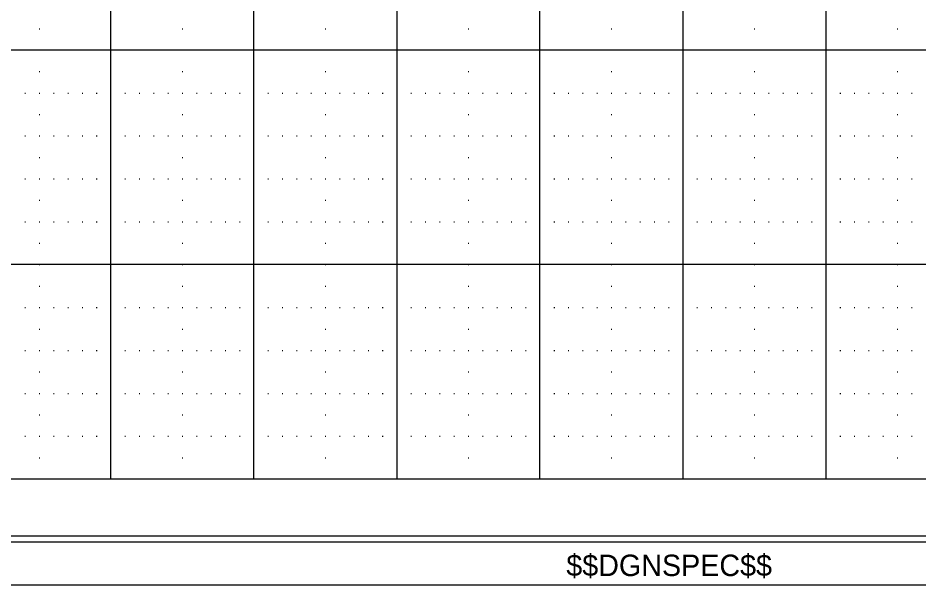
# Model space of a CAD drawing. Extents: x -1.3 to 32, y -0.2 to 20.7.
# Drawn here: x 23.679 to 27.879, y -0.229 to 2.414 of the extents above; entities that cross this region are included whole.
import ezdxf

# ---------------------------------------------------------------- set-up
doc = ezdxf.new("R2010")
doc.units = 0
for name, color, linetype in [('Level 1', 7, 'Continuous'), ('Level 37', 7, 'Continuous'), ('Level 4', 7, 'Continuous'), ('Level 48', 7, 'Continuous'), ('Level 5', 7, 'Continuous'), ('Level 62', 7, 'Continuous'), ('Level 63', 7, 'Continuous')]:
    doc.layers.add(name, color=color, linetype=linetype)

msp = doc.modelspace()

# ---------------------------------------------------------------- linework, layer by layer
at = {"layer": 'Level 1'}
msp.add_line((31.588, -0.03), (-0.03, -0.03), dxfattribs=at)
at = {"layer": 'Level 37'}
msp.add_line((31.1123, 0.264), (0.7787, 0.2635), dxfattribs=at)
at = {"layer": 'Level 4'}
for p, q in [((24.1123, 0.264), (24.1123, 10.264)), ((24.779, 0.264), (24.779, 10.264)), ((25.4457, 0.264), (25.4457, 10.264)), ((26.1123, 0.264), (26.1123, 10.264)), ((26.779, 0.264), (26.779, 10.264)), ((27.4457, 0.264), (27.4457, 10.264)), ((31.588, 2.264), (-0.03, 2.264)), ((31.588, 1.264), (-0.03, 1.264)), ((31.588, 0.264), (0.4456, 0.264))]:
    msp.add_line(p, q, dxfattribs=at)
at = {"layer": 'Level 5'}
for p, q in [((23.7773, 2.364), (23.7807, 2.364)), ((24.444, 2.364), (24.4473, 2.364)), ((25.1107, 2.364), (25.114, 2.364)), ((25.7773, 2.364), (25.7807, 2.364)), ((26.444, 2.364), (26.4473, 2.364)), ((27.1107, 2.364), (27.114, 2.364)), ((27.7773, 2.364), (27.7807, 2.364)), ((23.7773, 2.164), (23.7807, 2.164)), ((24.444, 2.164), (24.4473, 2.164)), ((25.1107, 2.164), (25.114, 2.164)), ((25.7773, 2.164), (25.7807, 2.164)), ((26.444, 2.164), (26.4473, 2.164)), ((27.1107, 2.164), (27.114, 2.164)), ((27.7773, 2.164), (27.7807, 2.164)), ((23.7107, 2.064), (23.714, 2.064)), ((23.7773, 2.064), (23.7807, 2.064)), ((23.844, 2.064), (23.8473, 2.064)), ((23.9107, 2.064), (23.914, 2.064)), ((23.9773, 2.064), (23.9807, 2.064)), ((24.044, 2.064), (24.0473, 2.064)), ((24.1773, 2.064), (24.1807, 2.064)), ((24.244, 2.064), (24.2473, 2.064)), ((24.3107, 2.064), (24.314, 2.064)), ((24.3773, 2.064), (24.3807, 2.064)), ((24.444, 2.064), (24.4473, 2.064)), ((24.5107, 2.064), (24.514, 2.064)), ((24.5773, 2.064), (24.5807, 2.064)), ((24.644, 2.064), (24.6473, 2.064)), ((24.7107, 2.064), (24.714, 2.064)), ((24.844, 2.064), (24.8473, 2.064)), ((24.9107, 2.064), (24.914, 2.064)), ((24.9773, 2.064), (24.9807, 2.064)), ((25.044, 2.064), (25.0473, 2.064)), ((25.1107, 2.064), (25.114, 2.064)), ((25.1773, 2.064), (25.1807, 2.064)), ((25.244, 2.064), (25.2473, 2.064)), ((25.3107, 2.064), (25.314, 2.064)), ((25.3773, 2.064), (25.3807, 2.064)), ((25.5107, 2.064), (25.514, 2.064)), ((25.5773, 2.064), (25.5807, 2.064)), ((25.644, 2.064), (25.6473, 2.064)), ((25.7107, 2.064), (25.714, 2.064)), ((25.7773, 2.064), (25.7807, 2.064)), ((25.844, 2.064), (25.8473, 2.064)), ((25.9107, 2.064), (25.914, 2.064)), ((25.9773, 2.064), (25.9807, 2.064)), ((26.044, 2.064), (26.0473, 2.064)), ((26.1773, 2.064), (26.1807, 2.064)), ((26.244, 2.064), (26.2473, 2.064)), ((26.3107, 2.064), (26.314, 2.064)), ((26.3773, 2.064), (26.3807, 2.064)), ((26.444, 2.064), (26.4473, 2.064)), ((26.5107, 2.064), (26.514, 2.064)), ((26.5773, 2.064), (26.5807, 2.064)), ((26.644, 2.064), (26.6473, 2.064)), ((26.7107, 2.064), (26.714, 2.064)), ((26.844, 2.064), (26.8473, 2.064)), ((26.9107, 2.064), (26.914, 2.064)), ((26.9773, 2.064), (26.9807, 2.064)), ((27.044, 2.064), (27.0473, 2.064)), ((27.1107, 2.064), (27.114, 2.064)), ((27.1773, 2.064), (27.1807, 2.064)), ((27.244, 2.064), (27.2473, 2.064)), ((27.3107, 2.064), (27.314, 2.064)), ((27.3773, 2.064), (27.3807, 2.064)), ((27.5107, 2.064), (27.514, 2.064)), ((27.5773, 2.064), (27.5807, 2.064)), ((27.644, 2.064), (27.6473, 2.064)), ((27.7107, 2.064), (27.714, 2.064)), ((27.7773, 2.064), (27.7807, 2.064)), ((27.844, 2.064), (27.8473, 2.064)), ((23.7773, 1.964), (23.7807, 1.964)), ((24.444, 1.964), (24.4473, 1.964)), ((25.1107, 1.964), (25.114, 1.964)), ((25.7773, 1.964), (25.7807, 1.964)), ((26.444, 1.964), (26.4473, 1.964)), ((27.1107, 1.964), (27.114, 1.964)), ((27.7773, 1.964), (27.7807, 1.964)), ((23.7107, 1.864), (23.714, 1.864)), ((23.7773, 1.864), (23.7807, 1.864)), ((23.844, 1.864), (23.8473, 1.864)), ((23.9107, 1.864), (23.914, 1.864)), ((23.9773, 1.864), (23.9807, 1.864)), ((24.044, 1.864), (24.0473, 1.864)), ((24.1773, 1.864), (24.1807, 1.864)), ((24.244, 1.864), (24.2473, 1.864)), ((24.3107, 1.864), (24.314, 1.864)), ((24.3773, 1.864), (24.3807, 1.864)), ((24.444, 1.864), (24.4473, 1.864)), ((24.5107, 1.864), (24.514, 1.864)), ((24.5773, 1.864), (24.5807, 1.864)), ((24.644, 1.864), (24.6473, 1.864)), ((24.7107, 1.864), (24.714, 1.864)), ((24.844, 1.864), (24.8473, 1.864)), ((24.9107, 1.864), (24.914, 1.864)), ((24.9773, 1.864), (24.9807, 1.864)), ((25.044, 1.864), (25.0473, 1.864)), ((25.1107, 1.864), (25.114, 1.864)), ((25.1773, 1.864), (25.1807, 1.864)), ((25.244, 1.864), (25.2473, 1.864)), ((25.3107, 1.864), (25.314, 1.864)), ((25.3773, 1.864), (25.3807, 1.864)), ((25.5107, 1.864), (25.514, 1.864)), ((25.5773, 1.864), (25.5807, 1.864)), ((25.644, 1.864), (25.6473, 1.864)), ((25.7107, 1.864), (25.714, 1.864)), ((25.7773, 1.864), (25.7807, 1.864)), ((25.844, 1.864), (25.8473, 1.864)), ((25.9107, 1.864), (25.914, 1.864)), ((25.9773, 1.864), (25.9807, 1.864)), ((26.044, 1.864), (26.0473, 1.864)), ((26.1773, 1.864), (26.1807, 1.864)), ((26.244, 1.864), (26.2473, 1.864)), ((26.3107, 1.864), (26.314, 1.864)), ((26.3773, 1.864), (26.3807, 1.864)), ((26.444, 1.864), (26.4473, 1.864)), ((26.5107, 1.864), (26.514, 1.864)), ((26.5773, 1.864), (26.5807, 1.864)), ((26.644, 1.864), (26.6473, 1.864)), ((26.7107, 1.864), (26.714, 1.864)), ((26.844, 1.864), (26.8473, 1.864)), ((26.9107, 1.864), (26.914, 1.864)), ((26.9773, 1.864), (26.9807, 1.864)), ((27.044, 1.864), (27.0473, 1.864)), ((27.1107, 1.864), (27.114, 1.864)), ((27.1773, 1.864), (27.1807, 1.864)), ((27.244, 1.864), (27.2473, 1.864)), ((27.3107, 1.864), (27.314, 1.864)), ((27.3773, 1.864), (27.3807, 1.864)), ((27.5107, 1.864), (27.514, 1.864)), ((27.5773, 1.864), (27.5807, 1.864)), ((27.644, 1.864), (27.6473, 1.864)), ((27.7107, 1.864), (27.714, 1.864)), ((27.7773, 1.864), (27.7807, 1.864)), ((27.844, 1.864), (27.8473, 1.864)), ((23.7773, 1.764), (23.7807, 1.764)), ((24.444, 1.764), (24.4473, 1.764)), ((25.1107, 1.764), (25.114, 1.764)), ((25.7773, 1.764), (25.7807, 1.764)), ((26.444, 1.764), (26.4473, 1.764)), ((27.1107, 1.764), (27.114, 1.764)), ((27.7773, 1.764), (27.7807, 1.764)), ((23.7107, 1.664), (23.714, 1.664)), ((23.7773, 1.664), (23.7807, 1.664)), ((23.844, 1.664), (23.8473, 1.664)), ((23.9107, 1.664), (23.914, 1.664)), ((23.9773, 1.664), (23.9807, 1.664)), ((24.044, 1.664), (24.0473, 1.664)), ((24.1773, 1.664), (24.1807, 1.664)), ((24.244, 1.664), (24.2473, 1.664)), ((24.3107, 1.664), (24.314, 1.664)), ((24.3773, 1.664), (24.3807, 1.664)), ((24.444, 1.664), (24.4473, 1.664)), ((24.5107, 1.664), (24.514, 1.664)), ((24.5773, 1.664), (24.5807, 1.664)), ((24.644, 1.664), (24.6473, 1.664)), ((24.7107, 1.664), (24.714, 1.664)), ((24.844, 1.664), (24.8473, 1.664)), ((24.9107, 1.664), (24.914, 1.664)), ((24.9773, 1.664), (24.9807, 1.664)), ((25.044, 1.664), (25.0473, 1.664)), ((25.1107, 1.664), (25.114, 1.664)), ((25.1773, 1.664), (25.1807, 1.664)), ((25.244, 1.664), (25.2473, 1.664)), ((25.3107, 1.664), (25.314, 1.664)), ((25.3773, 1.664), (25.3807, 1.664)), ((25.5107, 1.664), (25.514, 1.664)), ((25.5773, 1.664), (25.5807, 1.664)), ((25.644, 1.664), (25.6473, 1.664)), ((25.7107, 1.664), (25.714, 1.664)), ((25.7773, 1.664), (25.7807, 1.664)), ((25.844, 1.664), (25.8473, 1.664)), ((25.9107, 1.664), (25.914, 1.664)), ((25.9773, 1.664), (25.9807, 1.664)), ((26.044, 1.664), (26.0473, 1.664)), ((26.1773, 1.664), (26.1807, 1.664)), ((26.244, 1.664), (26.2473, 1.664)), ((26.3107, 1.664), (26.314, 1.664)), ((26.3773, 1.664), (26.3807, 1.664)), ((26.444, 1.664), (26.4473, 1.664)), ((26.5107, 1.664), (26.514, 1.664)), ((26.5773, 1.664), (26.5807, 1.664)), ((26.644, 1.664), (26.6473, 1.664)), ((26.7107, 1.664), (26.714, 1.664)), ((26.844, 1.664), (26.8473, 1.664)), ((26.9107, 1.664), (26.914, 1.664)), ((26.9773, 1.664), (26.9807, 1.664)), ((27.044, 1.664), (27.0473, 1.664)), ((27.1107, 1.664), (27.114, 1.664)), ((27.1773, 1.664), (27.1807, 1.664)), ((27.244, 1.664), (27.2473, 1.664)), ((27.3107, 1.664), (27.314, 1.664)), ((27.3773, 1.664), (27.3807, 1.664)), ((27.5107, 1.664), (27.514, 1.664)), ((27.5773, 1.664), (27.5807, 1.664)), ((27.644, 1.664), (27.6473, 1.664)), ((27.7107, 1.664), (27.714, 1.664)), ((27.7773, 1.664), (27.7807, 1.664)), ((27.844, 1.664), (27.8473, 1.664)), ((23.7773, 1.564), (23.7807, 1.564)), ((24.444, 1.564), (24.4473, 1.564)), ((25.1107, 1.564), (25.114, 1.564)), ((25.7773, 1.564), (25.7807, 1.564)), ((26.444, 1.564), (26.4473, 1.564)), ((27.1107, 1.564), (27.114, 1.564)), ((27.7773, 1.564), (27.7807, 1.564)), ((23.7107, 1.464), (23.714, 1.464)), ((23.7773, 1.464), (23.7807, 1.464)), ((23.844, 1.464), (23.8473, 1.464)), ((23.9107, 1.464), (23.914, 1.464)), ((23.9773, 1.464), (23.9807, 1.464)), ((24.044, 1.464), (24.0473, 1.464)), ((24.1773, 1.464), (24.1807, 1.464)), ((24.244, 1.464), (24.2473, 1.464)), ((24.3107, 1.464), (24.314, 1.464)), ((24.3773, 1.464), (24.3807, 1.464)), ((24.444, 1.464), (24.4473, 1.464)), ((24.5107, 1.464), (24.514, 1.464)), ((24.5773, 1.464), (24.5807, 1.464)), ((24.644, 1.464), (24.6473, 1.464)), ((24.7107, 1.464), (24.714, 1.464)), ((24.844, 1.464), (24.8473, 1.464)), ((24.9107, 1.464), (24.914, 1.464)), ((24.9773, 1.464), (24.9807, 1.464)), ((25.044, 1.464), (25.0473, 1.464)), ((25.1107, 1.464), (25.114, 1.464)), ((25.1773, 1.464), (25.1807, 1.464)), ((25.244, 1.464), (25.2473, 1.464)), ((25.3107, 1.464), (25.314, 1.464)), ((25.3773, 1.464), (25.3807, 1.464)), ((25.5107, 1.464), (25.514, 1.464)), ((25.5773, 1.464), (25.5807, 1.464)), ((25.644, 1.464), (25.6473, 1.464)), ((25.7107, 1.464), (25.714, 1.464)), ((25.7773, 1.464), (25.7807, 1.464)), ((25.844, 1.464), (25.8473, 1.464)), ((25.9107, 1.464), (25.914, 1.464)), ((25.9773, 1.464), (25.9807, 1.464)), ((26.044, 1.464), (26.0473, 1.464)), ((26.1773, 1.464), (26.1807, 1.464)), ((26.244, 1.464), (26.2473, 1.464)), ((26.3107, 1.464), (26.314, 1.464)), ((26.3773, 1.464), (26.3807, 1.464)), ((26.444, 1.464), (26.4473, 1.464)), ((26.5107, 1.464), (26.514, 1.464)), ((26.5773, 1.464), (26.5807, 1.464)), ((26.644, 1.464), (26.6473, 1.464)), ((26.7107, 1.464), (26.714, 1.464)), ((26.844, 1.464), (26.8473, 1.464)), ((26.9107, 1.464), (26.914, 1.464)), ((26.9773, 1.464), (26.9807, 1.464)), ((27.044, 1.464), (27.0473, 1.464)), ((27.1107, 1.464), (27.114, 1.464)), ((27.1773, 1.464), (27.1807, 1.464)), ((27.244, 1.464), (27.2473, 1.464)), ((27.3107, 1.464), (27.314, 1.464)), ((27.3773, 1.464), (27.3807, 1.464)), ((27.5107, 1.464), (27.514, 1.464)), ((27.5773, 1.464), (27.5807, 1.464)), ((27.644, 1.464), (27.6473, 1.464)), ((27.7107, 1.464), (27.714, 1.464)), ((27.7773, 1.464), (27.7807, 1.464)), ((27.844, 1.464), (27.8473, 1.464)), ((23.7773, 1.364), (23.7807, 1.364)), ((24.444, 1.364), (24.4473, 1.364)), ((25.1107, 1.364), (25.114, 1.364)), ((25.7773, 1.364), (25.7807, 1.364)), ((26.444, 1.364), (26.4473, 1.364)), ((27.1107, 1.364), (27.114, 1.364)), ((27.7773, 1.364), (27.7807, 1.364)), ((23.7773, 1.264), (23.7807, 1.264)), ((24.444, 1.264), (24.4473, 1.264)), ((25.1107, 1.264), (25.114, 1.264)), ((25.7773, 1.264), (25.7807, 1.264)), ((26.444, 1.264), (26.4473, 1.264)), ((27.1107, 1.264), (27.114, 1.264)), ((27.7773, 1.264), (27.7807, 1.264)), ((23.7773, 1.164), (23.7807, 1.164)), ((24.444, 1.164), (24.4473, 1.164)), ((25.1107, 1.164), (25.114, 1.164)), ((25.7773, 1.164), (25.7807, 1.164)), ((26.444, 1.164), (26.4473, 1.164)), ((27.1107, 1.164), (27.114, 1.164)), ((27.7773, 1.164), (27.7807, 1.164)), ((23.7107, 1.064), (23.714, 1.064)), ((23.7773, 1.064), (23.7807, 1.064)), ((23.844, 1.064), (23.8473, 1.064)), ((23.9107, 1.064), (23.914, 1.064)), ((23.9773, 1.064), (23.9807, 1.064)), ((24.044, 1.064), (24.0473, 1.064)), ((24.1773, 1.064), (24.1807, 1.064)), ((24.244, 1.064), (24.2473, 1.064)), ((24.3107, 1.064), (24.314, 1.064)), ((24.3773, 1.064), (24.3807, 1.064)), ((24.444, 1.064), (24.4473, 1.064)), ((24.5107, 1.064), (24.514, 1.064)), ((24.5773, 1.064), (24.5807, 1.064)), ((24.644, 1.064), (24.6473, 1.064)), ((24.7107, 1.064), (24.714, 1.064)), ((24.844, 1.064), (24.8473, 1.064)), ((24.9107, 1.064), (24.914, 1.064)), ((24.9773, 1.064), (24.9807, 1.064)), ((25.044, 1.064), (25.0473, 1.064)), ((25.1107, 1.064), (25.114, 1.064)), ((25.1773, 1.064), (25.1807, 1.064)), ((25.244, 1.064), (25.2473, 1.064)), ((25.3107, 1.064), (25.314, 1.064)), ((25.3773, 1.064), (25.3807, 1.064)), ((25.5107, 1.064), (25.514, 1.064)), ((25.5773, 1.064), (25.5807, 1.064)), ((25.644, 1.064), (25.6473, 1.064)), ((25.7107, 1.064), (25.714, 1.064)), ((25.7773, 1.064), (25.7807, 1.064)), ((25.844, 1.064), (25.8473, 1.064)), ((25.9107, 1.064), (25.914, 1.064)), ((25.9773, 1.064), (25.9807, 1.064)), ((26.044, 1.064), (26.0473, 1.064)), ((26.1773, 1.064), (26.1807, 1.064)), ((26.244, 1.064), (26.2473, 1.064)), ((26.3107, 1.064), (26.314, 1.064)), ((26.3773, 1.064), (26.3807, 1.064)), ((26.444, 1.064), (26.4473, 1.064)), ((26.5107, 1.064), (26.514, 1.064)), ((26.5773, 1.064), (26.5807, 1.064)), ((26.644, 1.064), (26.6473, 1.064)), ((26.7107, 1.064), (26.714, 1.064)), ((26.844, 1.064), (26.8473, 1.064)), ((26.9107, 1.064), (26.914, 1.064)), ((26.9773, 1.064), (26.9807, 1.064)), ((27.044, 1.064), (27.0473, 1.064)), ((27.1107, 1.064), (27.114, 1.064)), ((27.1773, 1.064), (27.1807, 1.064)), ((27.244, 1.064), (27.2473, 1.064)), ((27.3107, 1.064), (27.314, 1.064)), ((27.3773, 1.064), (27.3807, 1.064)), ((27.5107, 1.064), (27.514, 1.064)), ((27.5773, 1.064), (27.5807, 1.064)), ((27.644, 1.064), (27.6473, 1.064)), ((27.7107, 1.064), (27.714, 1.064)), ((27.7773, 1.064), (27.7807, 1.064)), ((27.844, 1.064), (27.8473, 1.064)), ((23.7773, 0.964), (23.7807, 0.964)), ((24.444, 0.964), (24.4473, 0.964)), ((25.1107, 0.964), (25.114, 0.964)), ((25.7773, 0.964), (25.7807, 0.964)), ((26.444, 0.964), (26.4473, 0.964)), ((27.1107, 0.964), (27.114, 0.964)), ((27.7773, 0.964), (27.7807, 0.964)), ((23.7107, 0.864), (23.714, 0.864)), ((23.7773, 0.864), (23.7807, 0.864)), ((23.844, 0.864), (23.8473, 0.864)), ((23.9107, 0.864), (23.914, 0.864)), ((23.9773, 0.864), (23.9807, 0.864)), ((24.044, 0.864), (24.0473, 0.864)), ((24.1773, 0.864), (24.1807, 0.864)), ((24.244, 0.864), (24.2473, 0.864)), ((24.3107, 0.864), (24.314, 0.864)), ((24.3773, 0.864), (24.3807, 0.864)), ((24.444, 0.864), (24.4473, 0.864)), ((24.5107, 0.864), (24.514, 0.864)), ((24.5773, 0.864), (24.5807, 0.864)), ((24.644, 0.864), (24.6473, 0.864)), ((24.7107, 0.864), (24.714, 0.864)), ((24.844, 0.864), (24.8473, 0.864)), ((24.9107, 0.864), (24.914, 0.864)), ((24.9773, 0.864), (24.9807, 0.864)), ((25.044, 0.864), (25.0473, 0.864)), ((25.1107, 0.864), (25.114, 0.864)), ((25.1773, 0.864), (25.1807, 0.864)), ((25.244, 0.864), (25.2473, 0.864)), ((25.3107, 0.864), (25.314, 0.864)), ((25.3773, 0.864), (25.3807, 0.864)), ((25.5107, 0.864), (25.514, 0.864)), ((25.5773, 0.864), (25.5807, 0.864)), ((25.644, 0.864), (25.6473, 0.864)), ((25.7107, 0.864), (25.714, 0.864)), ((25.7773, 0.864), (25.7807, 0.864)), ((25.844, 0.864), (25.8473, 0.864)), ((25.9107, 0.864), (25.914, 0.864)), ((25.9773, 0.864), (25.9807, 0.864)), ((26.044, 0.864), (26.0473, 0.864)), ((26.1773, 0.864), (26.1807, 0.864)), ((26.244, 0.864), (26.2473, 0.864)), ((26.3107, 0.864), (26.314, 0.864)), ((26.3773, 0.864), (26.3807, 0.864)), ((26.444, 0.864), (26.4473, 0.864)), ((26.5107, 0.864), (26.514, 0.864)), ((26.5773, 0.864), (26.5807, 0.864)), ((26.644, 0.864), (26.6473, 0.864)), ((26.7107, 0.864), (26.714, 0.864)), ((26.844, 0.864), (26.8473, 0.864)), ((26.9107, 0.864), (26.914, 0.864)), ((26.9773, 0.864), (26.9807, 0.864)), ((27.044, 0.864), (27.0473, 0.864)), ((27.1107, 0.864), (27.114, 0.864)), ((27.1773, 0.864), (27.1807, 0.864)), ((27.244, 0.864), (27.2473, 0.864)), ((27.3107, 0.864), (27.314, 0.864)), ((27.3773, 0.864), (27.3807, 0.864)), ((27.5107, 0.864), (27.514, 0.864)), ((27.5773, 0.864), (27.5807, 0.864)), ((27.644, 0.864), (27.6473, 0.864)), ((27.7107, 0.864), (27.714, 0.864)), ((27.7773, 0.864), (27.7807, 0.864)), ((27.844, 0.864), (27.8473, 0.864)), ((23.7773, 0.764), (23.7807, 0.764)), ((24.444, 0.764), (24.4473, 0.764)), ((25.1107, 0.764), (25.114, 0.764)), ((25.7773, 0.764), (25.7807, 0.764)), ((26.444, 0.764), (26.4473, 0.764)), ((27.1107, 0.764), (27.114, 0.764)), ((27.7773, 0.764), (27.7807, 0.764)), ((23.7107, 0.664), (23.714, 0.664)), ((23.7773, 0.664), (23.7807, 0.664)), ((23.844, 0.664), (23.8473, 0.664)), ((23.9107, 0.664), (23.914, 0.664)), ((23.9773, 0.664), (23.9807, 0.664)), ((24.044, 0.664), (24.0473, 0.664)), ((24.1773, 0.664), (24.1807, 0.664)), ((24.244, 0.664), (24.2473, 0.664)), ((24.3107, 0.664), (24.314, 0.664)), ((24.3773, 0.664), (24.3807, 0.664)), ((24.444, 0.664), (24.4473, 0.664)), ((24.5107, 0.664), (24.514, 0.664)), ((24.5773, 0.664), (24.5807, 0.664)), ((24.644, 0.664), (24.6473, 0.664)), ((24.7107, 0.664), (24.714, 0.664)), ((24.844, 0.664), (24.8473, 0.664)), ((24.9107, 0.664), (24.914, 0.664)), ((24.9773, 0.664), (24.9807, 0.664)), ((25.044, 0.664), (25.0473, 0.664)), ((25.1107, 0.664), (25.114, 0.664)), ((25.1773, 0.664), (25.1807, 0.664)), ((25.244, 0.664), (25.2473, 0.664)), ((25.3107, 0.664), (25.314, 0.664)), ((25.3773, 0.664), (25.3807, 0.664)), ((25.5107, 0.664), (25.514, 0.664)), ((25.5773, 0.664), (25.5807, 0.664)), ((25.644, 0.664), (25.6473, 0.664)), ((25.7107, 0.664), (25.714, 0.664)), ((25.7773, 0.664), (25.7807, 0.664)), ((25.844, 0.664), (25.8473, 0.664)), ((25.9107, 0.664), (25.914, 0.664)), ((25.9773, 0.664), (25.9807, 0.664)), ((26.044, 0.664), (26.0473, 0.664)), ((26.1773, 0.664), (26.1807, 0.664)), ((26.244, 0.664), (26.2473, 0.664)), ((26.3107, 0.664), (26.314, 0.664)), ((26.3773, 0.664), (26.3807, 0.664)), ((26.444, 0.664), (26.4473, 0.664)), ((26.5107, 0.664), (26.514, 0.664)), ((26.5773, 0.664), (26.5807, 0.664)), ((26.644, 0.664), (26.6473, 0.664)), ((26.7107, 0.664), (26.714, 0.664)), ((26.844, 0.664), (26.8473, 0.664)), ((26.9107, 0.664), (26.914, 0.664)), ((26.9773, 0.664), (26.9807, 0.664)), ((27.044, 0.664), (27.0473, 0.664)), ((27.1107, 0.664), (27.114, 0.664)), ((27.1773, 0.664), (27.1807, 0.664)), ((27.244, 0.664), (27.2473, 0.664)), ((27.3107, 0.664), (27.314, 0.664)), ((27.3773, 0.664), (27.3807, 0.664)), ((27.5107, 0.664), (27.514, 0.664)), ((27.5773, 0.664), (27.5807, 0.664)), ((27.644, 0.664), (27.6473, 0.664)), ((27.7107, 0.664), (27.714, 0.664)), ((27.7773, 0.664), (27.7807, 0.664)), ((27.844, 0.664), (27.8473, 0.664)), ((23.7773, 0.564), (23.7807, 0.564)), ((24.444, 0.564), (24.4473, 0.564)), ((25.1107, 0.564), (25.114, 0.564)), ((25.7773, 0.564), (25.7807, 0.564)), ((26.444, 0.564), (26.4473, 0.564)), ((27.1107, 0.564), (27.114, 0.564)), ((27.7773, 0.564), (27.7807, 0.564)), ((23.7107, 0.464), (23.714, 0.464)), ((23.7773, 0.464), (23.7807, 0.464)), ((23.844, 0.464), (23.8473, 0.464)), ((23.9107, 0.464), (23.914, 0.464)), ((23.9773, 0.464), (23.9807, 0.464)), ((24.044, 0.464), (24.0473, 0.464)), ((24.1773, 0.464), (24.1807, 0.464)), ((24.244, 0.464), (24.2473, 0.464)), ((24.3107, 0.464), (24.314, 0.464)), ((24.3773, 0.464), (24.3807, 0.464)), ((24.444, 0.464), (24.4473, 0.464)), ((24.5107, 0.464), (24.514, 0.464)), ((24.5773, 0.464), (24.5807, 0.464)), ((24.644, 0.464), (24.6473, 0.464)), ((24.7107, 0.464), (24.714, 0.464)), ((24.844, 0.464), (24.8473, 0.464)), ((24.9107, 0.464), (24.914, 0.464)), ((24.9773, 0.464), (24.9807, 0.464)), ((25.044, 0.464), (25.0473, 0.464)), ((25.1107, 0.464), (25.114, 0.464)), ((25.1773, 0.464), (25.1807, 0.464)), ((25.244, 0.464), (25.2473, 0.464)), ((25.3107, 0.464), (25.314, 0.464)), ((25.3773, 0.464), (25.3807, 0.464)), ((25.5107, 0.464), (25.514, 0.464)), ((25.5773, 0.464), (25.5807, 0.464)), ((25.644, 0.464), (25.6473, 0.464)), ((25.7107, 0.464), (25.714, 0.464)), ((25.7773, 0.464), (25.7807, 0.464)), ((25.844, 0.464), (25.8473, 0.464)), ((25.9107, 0.464), (25.914, 0.464)), ((25.9773, 0.464), (25.9807, 0.464)), ((26.044, 0.464), (26.0473, 0.464)), ((26.1773, 0.464), (26.1807, 0.464)), ((26.244, 0.464), (26.2473, 0.464)), ((26.3107, 0.464), (26.314, 0.464)), ((26.3773, 0.464), (26.3807, 0.464)), ((26.444, 0.464), (26.4473, 0.464)), ((26.5107, 0.464), (26.514, 0.464)), ((26.5773, 0.464), (26.5807, 0.464)), ((26.644, 0.464), (26.6473, 0.464)), ((26.7107, 0.464), (26.714, 0.464)), ((26.844, 0.464), (26.8473, 0.464)), ((26.9107, 0.464), (26.914, 0.464)), ((26.9773, 0.464), (26.9807, 0.464)), ((27.044, 0.464), (27.0473, 0.464)), ((27.1107, 0.464), (27.114, 0.464)), ((27.1773, 0.464), (27.1807, 0.464)), ((27.244, 0.464), (27.2473, 0.464)), ((27.3107, 0.464), (27.314, 0.464)), ((27.3773, 0.464), (27.3807, 0.464)), ((27.5107, 0.464), (27.514, 0.464)), ((27.5773, 0.464), (27.5807, 0.464)), ((27.644, 0.464), (27.6473, 0.464)), ((27.7107, 0.464), (27.714, 0.464)), ((27.7773, 0.464), (27.7807, 0.464)), ((27.844, 0.464), (27.8473, 0.464)), ((23.7773, 0.364), (23.7807, 0.364)), ((24.444, 0.364), (24.4473, 0.364)), ((25.1107, 0.364), (25.114, 0.364)), ((25.7773, 0.364), (25.7807, 0.364)), ((26.444, 0.364), (26.4473, 0.364)), ((27.1107, 0.364), (27.114, 0.364)), ((27.7773, 0.364), (27.7807, 0.364))]:
    msp.add_line(p, q, dxfattribs=at)
at = {"layer": 'Level 62'}
msp.add_line((2.4642, 0), (31.618, 0), dxfattribs=at)
at = {"layer": 'Level 63'}
msp.add_lwpolyline([(-1.292, -0.2295), (32.038, -0.2295), (32.038, 20.7175), (-1.292, 20.7175)], close=True, dxfattribs=at)

# ---------------------------------------------------------------- texts
at = {"layer": 'Level 48'}
msp.add_text('$$DGNSPEC$$', height=0.100002, dxfattribs=at).set_placement((26.235, -0.188))

doc.saveas('drawing.dxf')
